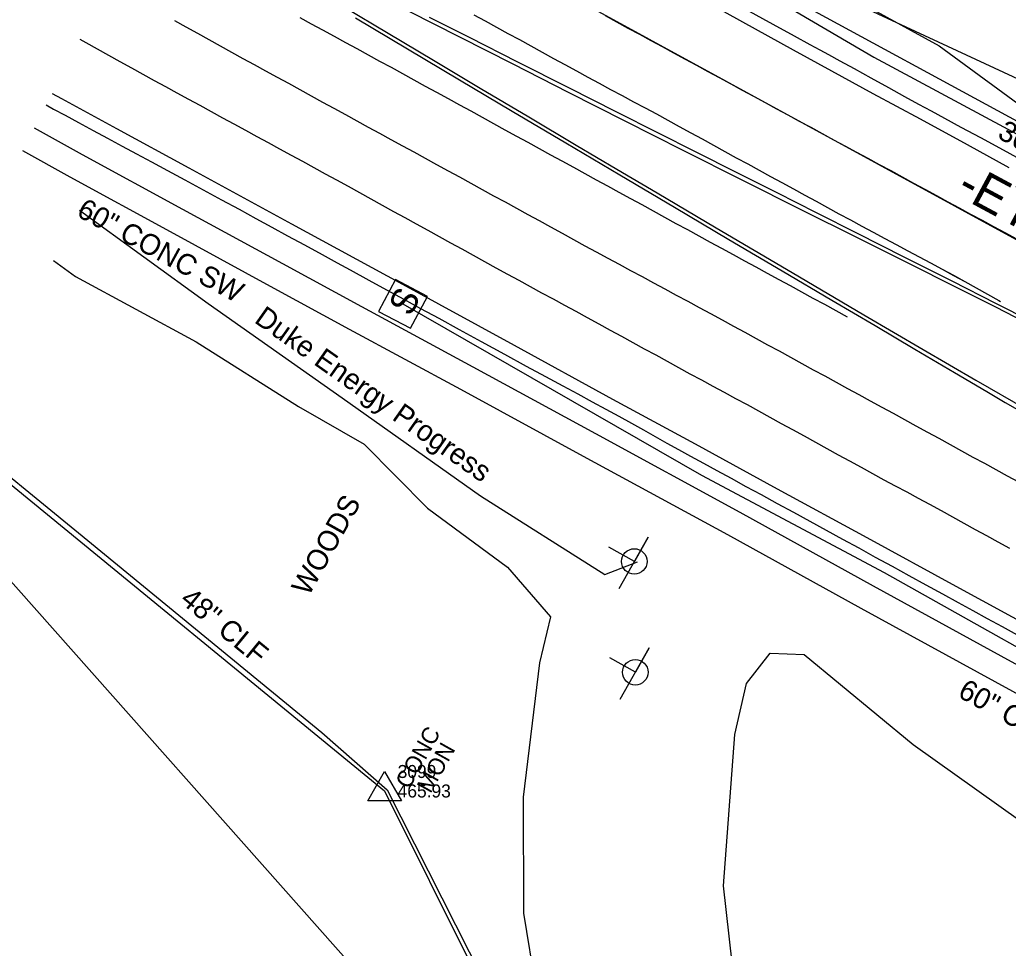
# Model space of a CAD drawing. Extents: x 2074109 to 2077820, y 741079 to 746031.
# Drawn here: x 2074733.4 to 2074923.4, y 743585.7 to 743764.3 of the extents above; entities that cross this region are included whole.
import ezdxf

# ---------------------------------------------------------------- set-up
doc = ezdxf.new("R2010")
doc.units = 0
for name, color, linetype in [('Exist Guardrail', 7, 'Continuous'), ('Exist Horizontal Alignment', 7, 'Continuous'), ('Exist Horizontal Alignment Direction Label', 7, 'Continuous'), ('Exist Other Culture Fence Line', 7, 'Continuous'), ('Exist Other Culture Fence Line Text', 7, 'Continuous'), ('Exist Right of Way Line', 7, 'Continuous'), ('Exist Right of Way Monument CELL', 7, 'Continuous'), ('Exist Right of Way Monument Cogo Elevation', 7, 'Continuous'), ('Exist Right of Way Monument Cogo Number', 7, 'Continuous'), ('Exist Right of Way Monument Text', 7, 'Continuous'), ('Exist Roads Curbs', 7, 'Continuous'), ('Exist Roads Curbs Text', 7, 'Continuous'), ('Exist Roads EOP', 7, 'Continuous'), ('Exist Roads EOP Other', 7, 'Continuous'), ('Exist Roads EOP Other Text', 7, 'Continuous'), ('Exist Roads EOT', 7, 'Continuous'), ('Exist Structure Minor Pipes RCP 30 Inch', 7, 'Continuous'), ('Exist Utilities Gas UG Line SUE LOS B', 7, 'Continuous'), ('Exist Utilities Other Traffic Signal Box CELL', 7, 'Continuous'), ('Exist Utilities Power Joint Use Telephone CELL', 7, 'Continuous'), ('Exist Utilities Power UG Cable SUE LOS B', 7, 'Continuous'), ('Exist Utilities Power UG Cable SUE LOS B Text', 7, 'Continuous'), ('Exist Utilities Telephone UG Conduit SUE LOS B', 7, 'Continuous'), ('Exist Utilities Water UG Line SUE LOS B', 7, 'Continuous'), ('Exist Vegetation Woods Line', 7, 'Continuous'), ('Exist Vegetation Woods Line Text', 7, 'Continuous')]:
    doc.layers.add(name, color=color, linetype=linetype)

msp = doc.modelspace()

# ---------------------------------------------------------------- linework, layer by layer
at = {"layer": 'Exist Guardrail'}
msp.add_lwpolyline([(2074832.64, 743795.43), (2074881.7, 743768.48), (2074925.82, 743744.41), (2074967.71, 743721.86), (2075006.03, 743700.89), (2075044.62, 743679.97), (2075070.51, 743665.74), (2075085.02, 743658.28), (2075094.95, 743653.63), (2075102.17, 743650.43), (2075105.47, 743649.62), (2075109.51, 743649.41), (2075116.13, 743649.75), (2075121.29, 743650.96), (2075127.34, 743652.97), (2075133.69, 743656.89), (2075139.72, 743662.07), (2075144.71, 743667.34), (2075149.22, 743673.57), (2075156.2, 743686.21), (2075174.08, 743720.03), (2075196.11, 743760.88), (2075206.48, 743780.84)], dxfattribs=at)
at = {"layer": 'Exist Horizontal Alignment'}
msp.add_line((2074769.18, 743807.11), (2075920.37, 743178.35), dxfattribs=at)
at = {"layer": 'Exist Other Culture Fence Line'}
msp.add_lwpolyline([(2074698.56, 743703.34), (2074744.67, 743665.63), (2074791.41, 743627.23), (2074803.99, 743616.2), (2074885.32, 743455.46), (2074895.68, 743434.26), (2074905.46, 743413.47), (2074907.79, 743389.11), (2074904.61, 743348.97), (2074900.56, 743289.13), (2074907.07, 743242.98), (2074904.29, 743222.49), (2074892.12, 743176.94), (2074886.91, 743117.55), (2074880.07, 743050.36), (2074879.15, 743002.6)], dxfattribs=at)
at = {"layer": 'Exist Right of Way Line'}
for p, q in [((2074602.77, 743780.53), (2074803.51, 743615.98)), ((2074803.51, 743615.98), (2074803.51, 743615.98)), ((2074803.51, 743615.98), (2074907.93, 743406.63))]:
    msp.add_line(p, q, dxfattribs=at)
at = {"layer": 'Exist Right of Way Monument CELL'}
msp.add_line((2074803.51, 743615.98), (2074803.51, 743615.98), dxfattribs=at)
msp.add_lwpolyline([(2074800.26, 743614.09), (2074803.51, 743619.73), (2074806.76, 743614.09)], close=True, dxfattribs=at)
at = {"layer": 'Exist Roads Curbs'}
for points in [[(2074795.77, 743766.73), (2074804.21, 743761.72), (2074812.92, 743756.52), (2074821.89, 743751.15), (2074831.2, 743745.61), (2074840.32, 743740.21), (2074848.13, 743735.59), (2074855.9, 743731), (2074867.23, 743724.31), (2074881.86, 743715.68), (2074895.63, 743707.57), (2074907.02, 743700.89), (2074917.19, 743694.96), (2074926.95, 743689.34)], [(2074872.92, 743766.35), (2074878.14, 743763.48), (2074882.25, 743761.22), (2074885.27, 743759.56), (2074887.2, 743758.5), (2074888.84, 743757.6), (2074891.03, 743756.4), (2074893.75, 743754.9), (2074897.01, 743753.1), (2074900.38, 743751.25), (2074903.44, 743749.57), (2074906.18, 743748.08), (2074908.6, 743746.76), (2074911.16, 743745.38), (2074914.31, 743743.66), (2074918.06, 743741.63), (2074922.41, 743739.26), (2074926.99, 743736.76)], [(2074926.59, 743706.13), (2074921.02, 743709.01), (2074913.35, 743712.88), (2074904.29, 743717.41), (2074894.43, 743722.33), (2074883.75, 743727.68), (2074872.39, 743733.4), (2074860.92, 743739.18), (2074849.75, 743744.8), (2074838.84, 743750.33), (2074828.2, 743755.76), (2074817.99, 743760.95), (2074808.22, 743765.87)], [(2074738.44, 743747.92), (2074739.85, 743747.13), (2074742.06, 743745.92), (2074744.66, 743744.51), (2074747.46, 743743), (2074750.24, 743741.5), (2074753.02, 743740), (2074755.79, 743738.52), (2074758.67, 743736.97), (2074761.76, 743735.31), (2074765.07, 743733.52), (2074768.6, 743731.61), (2074772.15, 743729.69), (2074775.54, 743727.85), (2074778.75, 743726.1), (2074781.8, 743724.43), (2074784.85, 743722.76), (2074788.08, 743721), (2074791.49, 743719.13), (2074794.37, 743717.56), (2074796.9, 743716.18), (2074800.46, 743714.24), (2074803.88, 743712.37), (2074807.18, 743710.57), (2074810.4, 743708.8), (2074813.93, 743706.88), (2074817.81, 743704.76), (2074822.06, 743702.44), (2074826.56, 743699.98), (2074830.72, 743697.71), (2074834.46, 743695.69), (2074837.77, 743693.9), (2074840.68, 743692.33), (2074843.43, 743690.85), (2074846.06, 743689.41), (2074848.55, 743688.04), (2074850.94, 743686.72), (2074853.26, 743685.42), (2074855.54, 743684.15), (2074857.78, 743682.9), (2074860, 743681.67), (2074862.33, 743680.38), (2074864.79, 743679.02), (2074867.38, 743677.6), (2074870.11, 743676.12), (2074872.95, 743674.57), (2074875.9, 743672.97), (2074878.96, 743671.3), (2074882.11, 743669.58), (2074885.27, 743667.86), (2074888.42, 743666.15), (2074891.55, 743664.43), (2074894.68, 743662.72), (2074897.85, 743660.98), (2074901.06, 743659.22), (2074904.31, 743657.43), (2074907.58, 743655.63), (2074910.74, 743653.9), (2074913.75, 743652.24), (2074916.62, 743650.67), (2074919.38, 743649.15), (2074922.21, 743647.6), (2074925.14, 743646)]]:
    msp.add_lwpolyline(points, dxfattribs=at)
at = {"layer": 'Exist Roads EOP'}
for points in [[(2074774.48, 743817.32), (2074781.93, 743813.25), (2074790.26, 743808.76), (2074797.6, 743804.81), (2074804.68, 743800.95), (2074813.78, 743795.97), (2074827.22, 743788.63), (2074842.02, 743780.55), (2074855.19, 743773.32), (2074866.27, 743767.22), (2074874.77, 743762.54), (2074882.04, 743758.54), (2074889.42, 743754.5), (2074897.4, 743750.15), (2074906.44, 743745.23), (2074915.49, 743740.3), (2074923.54, 743735.91)], [(2074797.9, 743764.66), (2074807.9, 743758.71), (2074817.92, 743752.75), (2074828.03, 743746.74), (2074838.32, 743740.65), (2074848.74, 743734.48), (2074859.23, 743728.24), (2074869.68, 743722.04), (2074879.94, 743715.99), (2074889.47, 743710.39), (2074897.79, 743705.49), (2074905.47, 743700.96), (2074913.06, 743696.46), (2074919.26, 743692.78), (2074922.82, 743690.67), (2074926.1, 743688.81)], [(2074927.6, 743706.42), (2074921.15, 743709.68), (2074912.6, 743714.01), (2074903.41, 743718.66), (2074894.45, 743723.19), (2074886.51, 743727.19), (2074878.95, 743730.99), (2074871.14, 743734.93), (2074863.4, 743738.84), (2074856.05, 743742.55), (2074848.18, 743746.53), (2074838.92, 743751.21), (2074829.14, 743756.16), (2074819.81, 743760.87), (2074812.15, 743764.74)], [(2074739.6, 743750.15), (2074741.36, 743749.14), (2074751.93, 743743.36), (2074765.85, 743735.8), (2074785.61, 743725.08), (2074806.97, 743713.44), (2074828.39, 743701.69), (2074847.33, 743691.36), (2074863.18, 743682.72), (2074878.97, 743674.08), (2074896.22, 743664.7), (2074913.35, 743655.38), (2074929.24, 743646.71)]]:
    msp.add_lwpolyline(points, dxfattribs=at)
at = {"layer": 'Exist Roads EOP Other'}
for points in [[(2074736.15, 743743.52), (2074745.36, 743738.39), (2074764.63, 743727.87), (2074783.88, 743717.41), (2074799.06, 743709.14), (2074820.47, 743697.56), (2074844.02, 743684.7), (2074871.78, 743669.61), (2074897.44, 743655.45), (2074932.64, 743636.17), (2074957.19, 743622.75), (2074981.37, 743609.53), (2075002.24, 743597.98), (2075030.68, 743582.18), (2075033.44, 743580.49), (2075037.68, 743577.54), (2075043.96, 743572.63), (2075050.45, 743567.5), (2075053.78, 743564.46), (2075055.44, 743566.25), (2075056.43, 743567.41)], [(2074733.88, 743739.15), (2074742.99, 743734.08), (2074762.28, 743723.55), (2074781.53, 743713.09), (2074796.71, 743704.81), (2074818.12, 743693.23), (2074841.67, 743680.38), (2074869.42, 743665.29), (2074895.07, 743651.14), (2074930.28, 743631.85), (2074954.82, 743618.43), (2074979, 743605.22), (2074999.86, 743593.68), (2075028.28, 743577.89), (2075030.72, 743576.39), (2075034.73, 743573.6), (2075040.92, 743568.76), (2075047.31, 743563.7), (2075054.69, 743557.36), (2075060.75, 743551.55), (2075061.79, 743551.62), (2075067.53, 743555.92)]]:
    msp.add_lwpolyline(points, dxfattribs=at)
at = {"layer": 'Exist Roads EOT'}
for points in [[(2074892.49, 743707.11), (2074890.3, 743708.31), (2074888.11, 743709.51), (2074885.91, 743710.71), (2074883.72, 743711.91), (2074881.53, 743713.11), (2074879.34, 743714.3), (2074877.14, 743715.5), (2074874.95, 743716.7), (2074872.75, 743717.9), (2074870.56, 743719.09), (2074868.37, 743720.29), (2074866.17, 743721.49), (2074863.98, 743722.68), (2074861.79, 743723.88), (2074859.59, 743725.08), (2074857.4, 743726.28), (2074855.21, 743727.48), (2074853.02, 743728.68), (2074850.82, 743729.88), (2074848.63, 743731.08), (2074846.44, 743732.28), (2074844.25, 743733.48), (2074842.06, 743734.68), (2074839.86, 743735.88), (2074837.67, 743737.08), (2074835.48, 743738.28), (2074833.29, 743739.48), (2074831.1, 743740.68), (2074828.9, 743741.88), (2074826.71, 743743.08), (2074824.52, 743744.28), (2074822.33, 743745.49), (2074820.14, 743746.69), (2074817.95, 743747.89), (2074815.76, 743749.09), (2074813.57, 743750.29), (2074811.38, 743751.49), (2074809.18, 743752.69), (2074806.99, 743753.89), (2074804.8, 743755.09), (2074802.61, 743756.29), (2074800.41, 743757.49), (2074798.22, 743758.69), (2074796.03, 743759.89), (2074793.84, 743761.09), (2074791.64, 743762.28), (2074789.45, 743763.48), (2074787.26, 743764.68)], [(2074820.64, 743765.27), (2074822.84, 743764.08), (2074825.03, 743762.88), (2074827.22, 743761.68), (2074829.41, 743760.48), (2074831.6, 743759.27), (2074833.79, 743758.07), (2074835.98, 743756.87), (2074838.18, 743755.67), (2074840.37, 743754.47), (2074842.57, 743753.28), (2074844.76, 743752.08), (2074846.96, 743750.88), (2074849.16, 743749.71), (2074851.36, 743748.53), (2074853.57, 743747.35), (2074855.77, 743746.18), (2074857.98, 743744.99), (2074860.16, 743743.79), (2074862.35, 743742.58), (2074864.54, 743741.37), (2074866.73, 743740.16), (2074868.92, 743738.96), (2074871.11, 743737.76), (2074873.31, 743736.57), (2074875.5, 743735.37), (2074877.7, 743734.18), (2074879.89, 743732.98), (2074882.09, 743731.78), (2074884.28, 743730.58), (2074886.47, 743729.39), (2074888.67, 743728.19), (2074890.86, 743727), (2074893.06, 743725.81), (2074895.26, 743724.63), (2074897.46, 743723.44), (2074899.66, 743722.26), (2074901.87, 743721.07), (2074904.07, 743719.89), (2074906.27, 743718.71), (2074908.48, 743717.53), (2074910.68, 743716.35), (2074912.87, 743715.14), (2074915.05, 743713.94), (2074917.24, 743712.73), (2074919.43, 743711.52), (2074921.62, 743710.31), (2074921.93, 743710.13)], [(2074820.65, 743765.27), (2074822.84, 743764.08), (2074825.03, 743762.88), (2074827.22, 743761.68), (2074829.41, 743760.48), (2074831.6, 743759.27), (2074833.79, 743758.07), (2074835.99, 743756.87), (2074838.18, 743755.67), (2074840.37, 743754.47), (2074842.57, 743753.28), (2074844.76, 743752.08), (2074846.96, 743750.88), (2074849.16, 743749.71), (2074851.37, 743748.53), (2074853.57, 743747.35), (2074855.77, 743746.18), (2074857.98, 743744.99), (2074860.16, 743743.79), (2074862.35, 743742.58), (2074864.54, 743741.37), (2074866.73, 743740.17), (2074868.92, 743738.96), (2074871.11, 743737.77), (2074873.31, 743736.57), (2074875.5, 743735.37), (2074877.7, 743734.18), (2074879.89, 743732.98), (2074882.09, 743731.78), (2074884.28, 743730.58), (2074886.47, 743729.39), (2074888.67, 743728.19), (2074890.86, 743727), (2074893.06, 743725.81), (2074895.26, 743724.63), (2074897.46, 743723.44), (2074899.66, 743722.26), (2074901.87, 743721.07), (2074904.07, 743719.89), (2074906.27, 743718.71), (2074908.48, 743717.53), (2074910.68, 743716.35), (2074912.87, 743715.15), (2074915.05, 743713.94), (2074917.24, 743712.73), (2074919.43, 743711.52), (2074921.62, 743710.31), (2074921.93, 743710.13)], [(2074845.89, 743765.09), (2074848.09, 743763.9), (2074850.28, 743762.71), (2074852.48, 743761.52), (2074854.68, 743760.32), (2074856.87, 743759.13), (2074859.07, 743757.94), (2074861.26, 743756.74), (2074863.46, 743755.55), (2074865.66, 743754.36), (2074867.85, 743753.17), (2074870.05, 743751.97), (2074872.24, 743750.78), (2074874.44, 743749.59), (2074876.64, 743748.39), (2074878.83, 743747.2), (2074881.03, 743746.01), (2074883.23, 743744.82), (2074885.42, 743743.63), (2074887.62, 743742.43), (2074889.82, 743741.24), (2074892.01, 743740.05), (2074894.21, 743738.86), (2074896.4, 743737.66), (2074898.6, 743736.47), (2074900.8, 743735.28), (2074902.99, 743734.09), (2074905.19, 743732.89), (2074907.38, 743731.7), (2074909.58, 743730.5), (2074911.78, 743729.31), (2074913.98, 743728.12), (2074916.17, 743726.93), (2074918.37, 743725.74), (2074920.57, 743724.55), (2074922.77, 743723.36), (2074924.96, 743722.17)], [(2074763.13, 743764.15), (2074765.31, 743762.93), (2074767.5, 743761.72), (2074769.68, 743760.5), (2074771.86, 743759.28), (2074774.05, 743758.08), (2074776.24, 743756.88), (2074778.43, 743755.68), (2074780.63, 743754.48), (2074782.82, 743753.28), (2074785.01, 743752.08), (2074787.2, 743750.88), (2074789.39, 743749.67), (2074791.58, 743748.47), (2074793.77, 743747.27), (2074795.97, 743746.07), (2074798.16, 743744.87), (2074800.35, 743743.67), (2074802.54, 743742.47), (2074804.73, 743741.27), (2074806.92, 743740.07), (2074809.12, 743738.87), (2074811.31, 743737.67), (2074813.5, 743736.47), (2074815.69, 743735.27), (2074817.89, 743734.07), (2074820.08, 743732.87), (2074822.27, 743731.67), (2074824.46, 743730.47), (2074826.65, 743729.27), (2074828.85, 743728.07), (2074831.04, 743726.87), (2074833.23, 743725.67), (2074835.42, 743724.46), (2074837.61, 743723.26), (2074839.8, 743722.06), (2074841.99, 743720.85), (2074844.19, 743719.66), (2074846.39, 743718.48), (2074848.59, 743717.29), (2074850.79, 743716.1), (2074852.99, 743714.91), (2074855.19, 743713.73), (2074857.38, 743712.54), (2074859.58, 743711.35), (2074861.78, 743710.16), (2074863.98, 743708.98), (2074866.18, 743707.79), (2074868.38, 743706.6), (2074870.57, 743705.4), (2074872.76, 743704.2), (2074874.95, 743703), (2074877.14, 743701.79), (2074879.34, 743700.6), (2074881.53, 743699.4), (2074883.72, 743698.2), (2074885.92, 743697), (2074888.11, 743695.8), (2074890.3, 743694.6), (2074892.5, 743693.41), (2074894.69, 743692.21), (2074896.88, 743691.01), (2074899.08, 743689.81), (2074901.27, 743688.61), (2074903.46, 743687.41), (2074905.66, 743686.21), (2074907.85, 743685.01), (2074910.04, 743683.82), (2074912.23, 743682.62), (2074914.43, 743681.41), (2074916.62, 743680.21), (2074918.81, 743679.01), (2074921, 743677.81), (2074923.19, 743676.61), (2074925.38, 743675.41)], [(2074923.68, 743662.61), (2074921.49, 743663.82), (2074919.3, 743665.03), (2074917.11, 743666.23), (2074914.92, 743667.44), (2074912.73, 743668.65), (2074910.55, 743669.85), (2074908.36, 743671.06), (2074906.16, 743672.25), (2074903.96, 743673.43), (2074901.75, 743674.61), (2074899.55, 743675.78), (2074897.35, 743676.98), (2074895.16, 743678.19), (2074892.97, 743679.39), (2074890.78, 743680.59), (2074888.59, 743681.8), (2074886.4, 743683), (2074884.21, 743684.2), (2074882.02, 743685.41), (2074879.83, 743686.61), (2074877.64, 743687.81), (2074875.45, 743689.01), (2074873.26, 743690.22), (2074871.06, 743691.42), (2074868.86, 743692.6), (2074866.67, 743693.79), (2074864.47, 743694.98), (2074862.27, 743696.17), (2074860.08, 743697.37), (2074857.89, 743698.57), (2074855.69, 743699.77), (2074853.5, 743700.97), (2074851.31, 743702.17), (2074849.12, 743703.37), (2074846.92, 743704.57), (2074844.73, 743705.77), (2074842.54, 743706.97), (2074840.35, 743708.17), (2074838.15, 743709.37), (2074835.96, 743710.57), (2074833.76, 743711.75), (2074831.56, 743712.94), (2074829.36, 743714.13), (2074827.17, 743715.33), (2074824.98, 743716.53), (2074822.79, 743717.74), (2074820.6, 743718.95), (2074818.41, 743720.15), (2074816.23, 743721.36), (2074814.04, 743722.56), (2074811.85, 743723.77), (2074809.66, 743724.97), (2074807.47, 743726.18), (2074805.28, 743727.39), (2074803.09, 743728.59), (2074800.9, 743729.8), (2074798.71, 743731), (2074796.53, 743732.21), (2074794.34, 743733.42), (2074792.15, 743734.62), (2074789.95, 743735.82), (2074787.76, 743737.01), (2074785.57, 743738.21), (2074783.37, 743739.41), (2074781.18, 743740.61), (2074778.99, 743741.8), (2074776.79, 743743), (2074774.6, 743744.2), (2074772.41, 743745.4), (2074770.21, 743746.59), (2074768.02, 743747.79), (2074765.83, 743748.99), (2074763.63, 743750.18), (2074761.44, 743751.38), (2074759.24, 743752.57), (2074757.05, 743753.77), (2074754.87, 743754.99), (2074752.69, 743756.22), (2074750.51, 743757.44), (2074748.32, 743758.65), (2074746.14, 743759.85), (2074744.97, 743760.5)]]:
    msp.add_lwpolyline(points, dxfattribs=at)
at = {"layer": 'Exist Structure Minor Pipes RCP 30 Inch'}
msp.add_line((2074655.41, 743742.16), (2074919.07, 743445.14), dxfattribs=at)
at = {"layer": 'Exist Utilities Gas UG Line SUE LOS B'}
msp.add_lwpolyline([(2074790.55, 743816.47), (2074800.77, 743810.96), (2074822.59, 743797.96), (2074869.08, 743773.86), (2074897.58, 743757.1), (2074956.84, 743725.22)], dxfattribs=at)
at = {"layer": 'Exist Utilities Other Traffic Signal Box CELL'}
msp.add_line((2074807.03, 743709.66), (2074807.03, 743709.66), dxfattribs=at)
msp.add_lwpolyline([(2074808.48, 743704.96), (2074811.72, 743711.11), (2074805.58, 743714.35), (2074802.33, 743708.21), (2074808.48, 743704.96)], dxfattribs=at)
at = {"layer": 'Exist Utilities Power Joint Use Telephone CELL'}
for p, q in [((2074851.52, 743660.12), (2074851.52, 743660.12)), ((2074851.7, 743638.81), (2074851.7, 743638.81))]:
    msp.add_line(p, q, dxfattribs=at)
for points in [[(2074848.61, 743654.95), (2074854.19, 743664.82), (2074851.53, 743660.12), (2074846.61, 743662.88)], [(2074848.79, 743633.63), (2074854.38, 743643.5), (2074851.72, 743638.8), (2074846.8, 743641.56)]]:
    msp.add_lwpolyline(points, dxfattribs=at)
for centre in [(2074851.51, 743660.13), (2074851.7, 743638.81)]:
    msp.add_circle(centre, 2.45, dxfattribs=at)
at = {"layer": 'Exist Utilities Power UG Cable SUE LOS B'}
for points in [[(2074744.82, 743727.66), (2074769.57, 743709.74), (2074795.32, 743691.58), (2074821.96, 743672.76), (2074845.86, 743657.6), (2074852.11, 743660.08)], [(2074807.97, 743711.12), (2074807.03, 743709.66), (2074864.42, 743676.69), (2074899.54, 743658.03), (2074946.14, 743631.83), (2074992.75, 743607.11), (2075019.25, 743592.31)]]:
    msp.add_lwpolyline(points, dxfattribs=at)
at = {"layer": 'Exist Utilities Telephone UG Conduit SUE LOS B'}
msp.add_lwpolyline([(2074852.23, 743796.93), (2074858.98, 743788.14), (2074871.16, 743780.09), (2074884.61, 743773.35), (2074910.14, 743759.3), (2074929.12, 743745.39), (2074958.42, 743728.87), (2074997.61, 743706.69), (2075052.29, 743677.02), (2075084.82, 743660.77), (2075107.9, 743645.87), (2075165.73, 743622.21), (2075198.81, 743604.97), (2075246.84, 743581.99), (2075289.9, 743561.06), (2075322.06, 743548.08), (2075339.73, 743539.52), (2075355.79, 743530.19), (2075360.13, 743528.64), (2075373.71, 743515.02), (2075393.05, 743495.87), (2075443.09, 743463.69), (2075672.89, 743341.39)], dxfattribs=at)
at = {"layer": 'Exist Utilities Water UG Line SUE LOS B'}
msp.add_lwpolyline([(2074661.41, 743894.07), (2074669.03, 743889.86), (2074695.78, 743877.33), (2074733.5, 743856.32), (2074766.19, 743837.03), (2074806.52, 743814.12), (2074828.36, 743801.4), (2074869.77, 743778.77), (2075138.71, 743653.82), (2075174.59, 743638.37), (2075261.38, 743603.22), (2075296.53, 743589.33), (2075345.56, 743568.62), (2075373.37, 743552.36), (2075399.34, 743536.02), (2075447.19, 743500.05), (2075713.36, 743360.43), (2075744.72, 743342.27), (2075764.85, 743330.17), (2075782.75, 743317.7), (2075822.78, 743289.56)], dxfattribs=at)
at = {"layer": 'Exist Vegetation Woods Line'}
for points in [[(2074739.86, 743718.03), (2074744.06, 743714.9), (2074767.25, 743702.37), (2074786.92, 743689.92), (2074799.59, 743682.67), (2074811.76, 743670.38), (2074827.15, 743659.04), (2074835.38, 743649.47), (2074833.26, 743640.61), (2074830.15, 743614.81), (2074830.23, 743592.49), (2074834.97, 743563.53), (2074834.45, 743543.48), (2074837.44, 743525.18), (2074840.25, 743508.01)], [(2074869.07, 743492.95), (2074870.22, 743547.74), (2074870.9, 743577.8), (2074868.69, 743597.73), (2074870.85, 743626.82), (2074873.07, 743636.67), (2074877.61, 743642.49), (2074884.16, 743642.22), (2074905.1, 743624.9), (2074958.77, 743586.73)]]:
    msp.add_lwpolyline(points, dxfattribs=at)

# ---------------------------------------------------------------- texts
at = {"layer": 'Exist Horizontal Alignment Direction Label'}
msp.add_text('-EY1-', height=7, rotation=331.6793, dxfattribs=at).set_placement((2074913.11, 743730.71))
at = {"layer": 'Exist Other Culture Fence Line Text'}
msp.add_text('48" CLF', height=4, rotation=320.6022, dxfattribs=at).set_placement((2074763.96, 743652.37))
at = {"layer": 'Exist Right of Way Monument Cogo Elevation'}
msp.add_text('465.93', height=2.5, dxfattribs=at).set_placement((2074806.01, 743614.73))
at = {"layer": 'Exist Right of Way Monument Cogo Number'}
msp.add_text('3099', height=2.5, dxfattribs=at).set_placement((2074806.01, 743618.48))
at = {"layer": 'Exist Right of Way Monument Text'}
for s, p in [('CONC', (2074808.19, 743616.18)), ('MON', (2074812.33, 743615.36))]:
    msp.add_text(s, height=3.2, rotation=60.742, dxfattribs=at).set_placement(p)
at = {"layer": 'Exist Roads Curbs Text'}
msp.add_text('30" C&G', height=4, rotation=331.3823, dxfattribs=at).set_placement((2074921.12, 743741.67))
at = {"layer": 'Exist Roads EOP Other Text'}
for rotation, p in [(331.3678, (2074744.06, 743726.66)), (331.3247, (2074913.49, 743634.2))]:
    msp.add_text('60" CONC SW', height=4, rotation=rotation, dxfattribs=at).set_placement(p)
at = {"layer": 'Exist Utilities Other Traffic Signal Box CELL'}
msp.add_text('S', height=5, rotation=62.1423, dxfattribs=at).set_placement((2074808.47, 743707.05))
at = {"layer": 'Exist Utilities Power UG Cable SUE LOS B Text'}
msp.add_text('Duke Energy Progress', height=4, rotation=324.7973, dxfattribs=at).set_placement((2074778.25, 743706.21))
at = {"layer": 'Exist Vegetation Woods Line Text'}
msp.add_text('WOODS', height=4, rotation=60.742, dxfattribs=at).set_placement((2074788.89, 743653.28))

doc.saveas('drawing.dxf')
